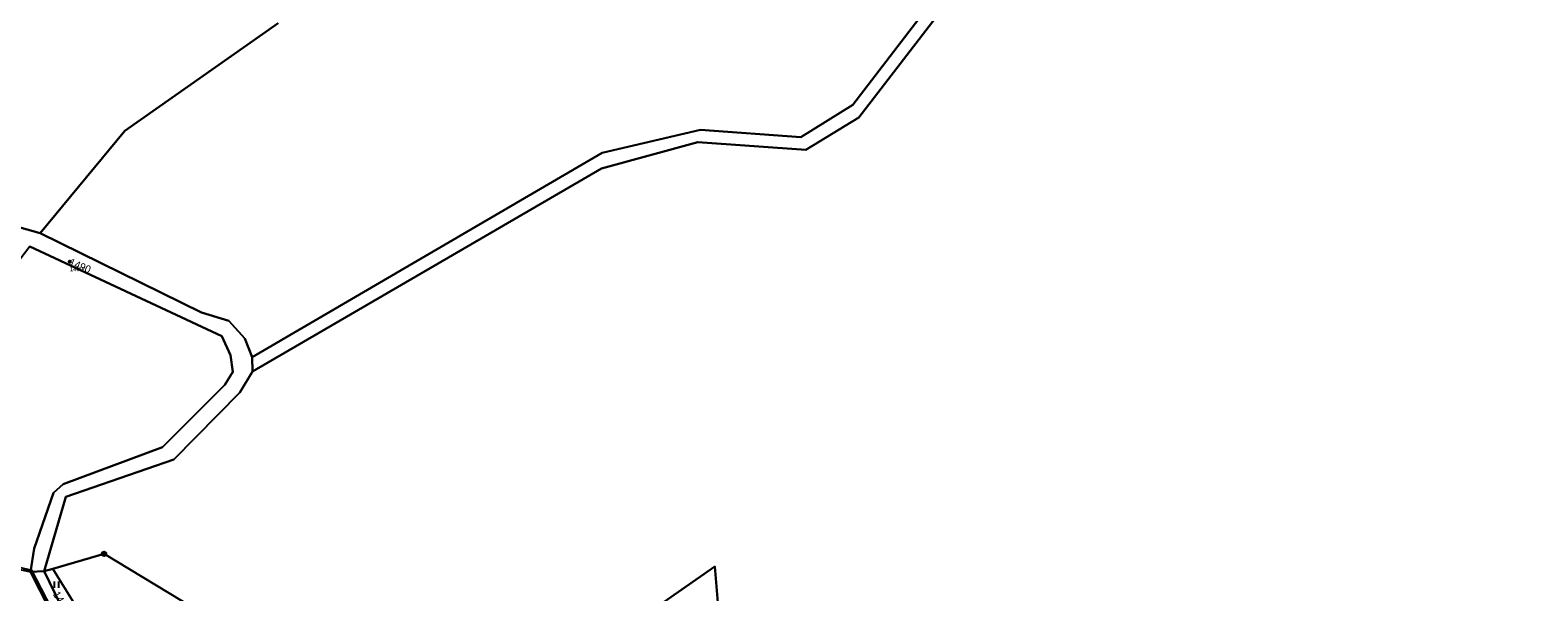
# Model space of a CAD drawing. Extents: x -770088 to -765625, y -1057899 to -1053934.
# Drawn here: x -766495.3 to -766152.2, y -1057643.3 to -1057515.4 of the extents above; entities that cross this region are included whole.
import ezdxf

# ---------------------------------------------------------------- set-up
doc = ezdxf.new("R2010")
doc.units = 0
for name, color, linetype in [('Definiční body', 7, 'Continuous'), ('Hranice parcel', 7, 'Continuous'), ('Parcelní čísla', 7, 'Continuous'), ('Polygon ku', 7, 'Continuous'), ('Polygon parcely', 7, 'Continuous'), ('Vnitřní kresba', 7, 'Continuous'), ('Značky bodu BP', 7, 'Continuous'), ('Značky kultur', 7, 'Continuous')]:
    doc.layers.add(name, color=color, linetype=linetype)

msp = doc.modelspace()

# ---------------------------------------------------------------- linework, layer by layer
at = {"layer": 'Definiční body'}
msp.add_circle((-766486.28, -1057568.12), 0.25, dxfattribs=at)
at = {"layer": 'Hranice parcel'}
for p, q in [((-766444.69, -1057593.13), (-766444.75, -1057589.83)), ((-766495.23, -1057638.72), (-766496.86, -1057638.35)), ((-766495.23, -1057638.72), (-766492.09, -1057638.58)), ((-766477.63, -1057673.02), (-766495.23, -1057638.72)), ((-766492.09, -1057638.58), (-766490.17, -1057638.02)), ((-766476.41, -1057670.88), (-766492.09, -1057638.58))]:
    msp.add_line(p, q, dxfattribs=at)
for points in [[(-766444.75, -1057589.83), (-766365.1, -1057543.33), (-766342.76, -1057538.11), (-766319.88, -1057539.8), (-766308.07, -1057532.45), (-766287.82, -1057505.98), (-766275.27, -1057493.67), (-766244.77, -1057474.92), (-766222.55, -1057452.14), (-766214.24, -1057436.33), (-766210.19, -1057407.67), (-766203.24, -1057390.14), (-766199.89, -1057364.85), (-766190.39, -1057348.9), (-766173.89, -1057334.5), (-766142.7, -1057319.35), (-766118, -1057309.79), (-766103.78, -1057298.93), (-766082.62, -1057277.26)], [(-766078.19, -1057276.68), (-766103.38, -1057302.46), (-766116.58, -1057312.37), (-766141.75, -1057321.7), (-766171.88, -1057336.39), (-766188.96, -1057351.5), (-766196.6, -1057365.36), (-766201.1, -1057392.12), (-766207.61, -1057409.29), (-766211.17, -1057435.3), (-766221.27, -1057454.72), (-766242.51, -1057476.49), (-766272.1, -1057495.52), (-766286.4, -1057508.94), (-766306.69, -1057535.33), (-766318.78, -1057542.64), (-766343.38, -1057540.91), (-766365.25, -1057546.9), (-766444.69, -1057593.13)], [(-766493.05, -1057561.65), (-766501.36, -1057559.27), (-766507.29, -1057556.2), (-766519.08, -1057549.02), (-766527.76, -1057539.29), (-766535.96, -1057528.62), (-766549.99, -1057505.62), (-766554.22, -1057499.25), (-766565.03, -1057485.85), (-766580.49, -1057465.37), (-766587.49, -1057452.79)], [(-766438.83, -1057513.87), (-766473.73, -1057538.34), (-766493.05, -1057561.65)], [(-766495.23, -1057638.72), (-766494.38, -1057633.43), (-766489.95, -1057620.72), (-766487.79, -1057618.74), (-766465.15, -1057610.35), (-766451.03, -1057596.16), (-766449.18, -1057593.2), (-766449.67, -1057589.37), (-766451.71, -1057585.09), (-766495.37, -1057564.67)], [(-766493.05, -1057561.65), (-766456.29, -1057579.68), (-766450.12, -1057581.6), (-766446.44, -1057585.61), (-766444.75, -1057589.83)], [(-766444.69, -1057593.13), (-766447.6, -1057597.9), (-766462.61, -1057613.14), (-766487.15, -1057621.64), (-766492.09, -1057638.58)], [(-766490.17, -1057638.02), (-766478.48, -1057634.61), (-766455.02, -1057648.83), (-766435.72, -1057649.95), (-766426.63, -1057660.74), (-766411.31, -1057660.26)], [(-766490.17, -1057638.02), (-766474.96, -1057662.55), (-766476.41, -1057670.88)], [(-766411.31, -1057660.26), (-766391.8, -1057659.17), (-766359.51, -1057651.44), (-766339.5, -1057637.5), (-766337.84, -1057657.51), (-766342.94, -1057679.46), (-766339.36, -1057686.09)]]:
    msp.add_lwpolyline(points, dxfattribs=at)
at = {"layer": 'Polygon ku'}
msp.add_lwpolyline([(-766496.86, -1057638.35), (-766495.23, -1057638.72), (-766477.63, -1057673.02)], dxfattribs=at)
at = {"layer": 'Polygon parcely'}
for points in [[(-766711.32, -1057498.92), (-766683.21, -1057521.4), (-766653.34, -1057550.89), (-766545.33, -1057618.55), (-766518.19, -1057630.05), (-766500.65, -1057637.48), (-766496.86, -1057638.35), (-766495.23, -1057638.72), (-766494.38, -1057633.43), (-766489.95, -1057620.72), (-766487.79, -1057618.74), (-766465.15, -1057610.35), (-766451.03, -1057596.16), (-766449.18, -1057593.2), (-766449.67, -1057589.37), (-766451.71, -1057585.09), (-766495.37, -1057564.67), (-766505.6, -1057578.03), (-766529.01, -1057560.4), (-766562.14, -1057580.69), (-766577.66, -1057542.43), (-766600.48, -1057486.17)], [(-766549.99, -1057505.62), (-766535.96, -1057528.62), (-766527.76, -1057539.29), (-766519.08, -1057549.02), (-766507.29, -1057556.2), (-766501.36, -1057559.27), (-766493.05, -1057561.65), (-766473.73, -1057538.34), (-766438.83, -1057513.87)], [(-766438.83, -1057513.87), (-766473.73, -1057538.34), (-766493.05, -1057561.65), (-766456.29, -1057579.68), (-766450.12, -1057581.6), (-766446.44, -1057585.61), (-766444.75, -1057589.83), (-766365.1, -1057543.33), (-766342.76, -1057538.11), (-766319.88, -1057539.8), (-766308.07, -1057532.45), (-766287.82, -1057505.98)], [(-766287.82, -1057505.98), (-766308.07, -1057532.45), (-766319.88, -1057539.8), (-766342.76, -1057538.11), (-766365.1, -1057543.33), (-766444.75, -1057589.83), (-766444.69, -1057593.13), (-766365.25, -1057546.9), (-766343.38, -1057540.91), (-766318.78, -1057542.64), (-766306.69, -1057535.33), (-766286.4, -1057508.94)], [(-766286.4, -1057508.94), (-766306.69, -1057535.33), (-766318.78, -1057542.64), (-766343.38, -1057540.91), (-766365.25, -1057546.9), (-766444.69, -1057593.13), (-766447.6, -1057597.9), (-766462.61, -1057613.14), (-766487.15, -1057621.64), (-766492.09, -1057638.58), (-766490.17, -1057638.02), (-766478.48, -1057634.61), (-766455.02, -1057648.83)], [(-766495.37, -1057564.67), (-766451.71, -1057585.09), (-766449.67, -1057589.37), (-766449.18, -1057593.2), (-766451.03, -1057596.16), (-766465.15, -1057610.35), (-766487.79, -1057618.74), (-766489.95, -1057620.72), (-766494.38, -1057633.43), (-766495.23, -1057638.72), (-766492.09, -1057638.58), (-766487.15, -1057621.64), (-766462.61, -1057613.14), (-766447.6, -1057597.9), (-766444.69, -1057593.13), (-766444.75, -1057589.83), (-766446.44, -1057585.61), (-766450.12, -1057581.6), (-766456.29, -1057579.68), (-766493.05, -1057561.65), (-766501.36, -1057559.27)], [(-766359.51, -1057651.44), (-766339.5, -1057637.5), (-766337.84, -1057657.51)]]:
    msp.add_lwpolyline(points, dxfattribs=at)
for points in [[(-766398.43, -1057765.38), (-766404.24, -1057716.57), (-766404.56, -1057713.99), (-766411.31, -1057660.26), (-766426.63, -1057660.74), (-766435.72, -1057649.95), (-766455.02, -1057648.83), (-766478.48, -1057634.61), (-766490.17, -1057638.02), (-766474.96, -1057662.55), (-766476.41, -1057670.88), (-766466.37, -1057684.4), (-766457.52, -1057699.58), (-766436.97, -1057750.17), (-766426.79, -1057776.67)], [(-766476.41, -1057670.88), (-766492.09, -1057638.58), (-766495.23, -1057638.72), (-766477.63, -1057673.02)], [(-766490.17, -1057638.02), (-766492.09, -1057638.58), (-766476.41, -1057670.88), (-766474.96, -1057662.55)], [(-766284.33, -1057730.61), (-766282.18, -1057722.5), (-766327.61, -1057699.31), (-766336.34, -1057692.08), (-766339.36, -1057686.09), (-766342.94, -1057679.46), (-766337.84, -1057657.51), (-766339.5, -1057637.5), (-766359.51, -1057651.44), (-766391.8, -1057659.17), (-766411.31, -1057660.26), (-766404.56, -1057713.99), (-766368.99, -1057697.17), (-766361.08, -1057698.3), (-766360.15, -1057701.4), (-766334.22, -1057710.05)]]:
    msp.add_lwpolyline(points, close=True, dxfattribs=at)
at = {"layer": 'Vnitřní kresba'}
for p in [(-766500.51, -1057637), (-766477.07, -1057673.02)]:
    msp.add_line(p, (-766494.88, -1057638.29), dxfattribs=at)
at = {"layer": 'Značky bodu BP'}
for radius in [0.5, 0.0303]:
    msp.add_circle((-766478.48, -1057634.61), radius, dxfattribs=at)
at = {"layer": 'Značky kultur'}
for p, q in [((-766489.78, -1057642.38), (-766489.78, -1057640.88)), ((-766488.78, -1057642.38), (-766488.78, -1057640.88))]:
    msp.add_line(p, q, dxfattribs=at)

# ---------------------------------------------------------------- texts
at = {"layer": 'Definiční body'}
msp.add_text('1490', height=1, dxfattribs=at).set_placement((-766486.28, -1057570.28))
at = {"layer": 'Parcelní čísla'}
for s, rotation, p in [('1490', 338, (-766486.6, -1057568.91)), ('1404/2', 302, (-766490.2, -1057643.8))]:
    msp.add_text(s, height=1.7, rotation=rotation, dxfattribs=at).set_placement(p)

doc.saveas('drawing.dxf')
